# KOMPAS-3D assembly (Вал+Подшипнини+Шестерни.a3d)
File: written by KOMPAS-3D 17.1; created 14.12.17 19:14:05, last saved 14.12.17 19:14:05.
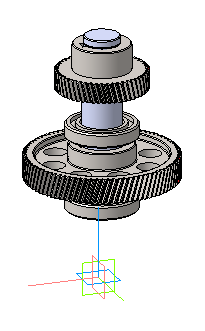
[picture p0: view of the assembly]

Referenced files in C:\Users\Yaroslav\Desktop\Новая папка\: Уплотнение.m3d, Шпонка (18х11х56).m3d, Вал.m3d, Косозубая шестерня 2 (правое)_PreviewCfg.m3d, Косозубая шестерня 3 (левое)_PreviewCfg.m3d, Шпонка (16х10х56).m3d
